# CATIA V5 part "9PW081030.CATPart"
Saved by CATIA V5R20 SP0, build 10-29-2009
Part number: 9PW081030
Revision: ANY
Definition: UNKNOWN
Nomenclature: 9PW081030
Source: Unknown
Bounding box of the stored display mesh (mm): x -174.5 to 0, y -11.573 to 4, z -5.1 to 5.1
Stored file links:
  C:\Users\Utente\Desktop\IO LAVORO\3D X SITO CF\CUMSA\3D files PW\pw081030\pw081030_ejection\9PW081030.CATPart
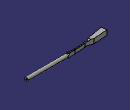
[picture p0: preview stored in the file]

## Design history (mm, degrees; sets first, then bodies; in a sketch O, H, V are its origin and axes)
Body1 "Chaflán2" (main body)
  Solid1: solid without history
